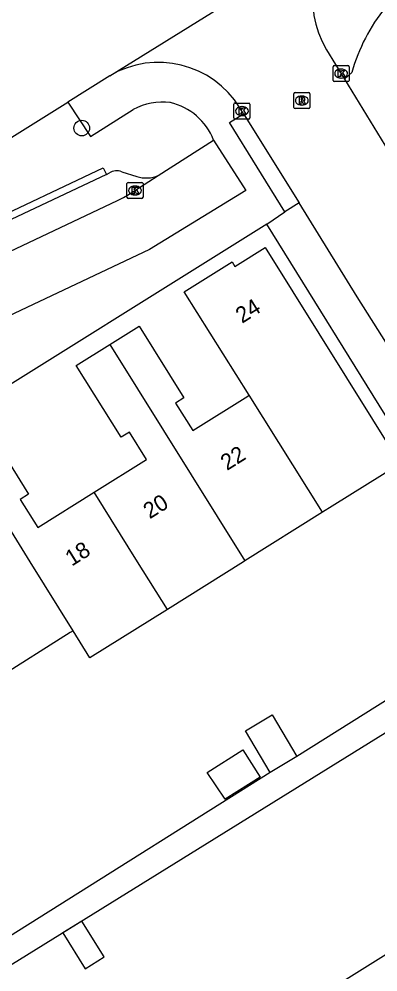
# Model space of a CAD drawing. Extents: x 157767 to 159171, y 387842 to 389425.
# Drawn here: x 158324.1 to 158346.5, y 388224.4 to 388283.9 of the extents above; entities that cross this region are included whole.
import ezdxf

# ---------------------------------------------------------------- set-up
doc = ezdxf.new("R2010")
doc.units = 0
for name, color, linetype in [('IMGEO_Boom', 7, 'Continuous'), ('IMGEO_Fietspad_open', 7, 'Continuous'), ('IMGEO_Kolk', 7, 'Continuous'), ('IMGEO_Pand', 7, 'Continuous'), ('IMGEO_Pand_nummerreeks', 7, 'Continuous'), ('IMGEO_Parkeervlak_open', 7, 'Continuous'), ('IMGEO_Rijbaan_lokaal_gesloten', 7, 'Continuous'), ('IMGEO_Rijbaan_lokaal_open', 7, 'Continuous'), ('IMGEO_Rioolput', 7, 'Continuous'), ('IMGEO_Voetpad_open', 7, 'Continuous')]:
    doc.layers.add(name, color=color, linetype=linetype)

msp = doc.modelspace()

# ---------------------------------------------------------------- linework, layer by layer
at = {"layer": 'IMGEO_Boom'}
msp.add_circle((158328.047, 388277.051), 0.489, dxfattribs=at)
at = {"layer": 'IMGEO_Fietspad_open'}
msp.add_lwpolyline([(158344.91, 388280.527), (158344.452, 388280.106)], dxfattribs=at)
msp.add_arc((158356.036, 388277.36), 11.568, 141.36415, 164.11301, dxfattribs=at)
at = {"layer": 'IMGEO_Kolk'}
for p, q in [((158343.74, 388280.027), (158343.74, 388280.879)), ((158343.815, 388280.953), (158344.667, 388280.953)), ((158344.228, 388280.733), (158344.253, 388280.733)), ((158344.741, 388280.879), (158344.741, 388280.027)), ((158344.667, 388279.953), (158343.815, 388279.953)), ((158344.251, 388280.173), (158344.226, 388280.173)), ((158337.621, 388278.616), (158338.473, 388278.616)), ((158337.546, 388277.69), (158337.546, 388278.542)), ((158338.034, 388278.396), (158338.059, 388278.396)), ((158338.547, 388278.542), (158338.547, 388277.69)), ((158338.473, 388277.616), (158337.621, 388277.616)), ((158338.057, 388277.836), (158338.032, 388277.836)), ((158330.869, 388272.732), (158330.869, 388273.584)), ((158330.944, 388273.658), (158331.796, 388273.658)), ((158331.357, 388273.438), (158331.382, 388273.438)), ((158331.87, 388273.584), (158331.87, 388272.732)), ((158331.796, 388272.658), (158330.944, 388272.658)), ((158331.38, 388272.878), (158331.355, 388272.878))]:
    msp.add_line(p, q, dxfattribs=at)
for points in [[(158343.74, 388280.027), (158343.74, 388280.879)], [(158343.815, 388280.953), (158344.667, 388280.953)], [(158344.061, 388280.653), (158344.184, 388280.653), (158344.184, 388280.502), (158344.314, 388280.653), (158344.478, 388280.653), (158344.332, 388280.502), (158344.485, 388280.253), (158344.333, 388280.253), (158344.248, 388280.417), (158344.184, 388280.35), (158344.184, 388280.253), (158344.061, 388280.253), (158344.061, 388280.653)], [(158344.741, 388280.879), (158344.741, 388280.027)], [(158344.667, 388279.953), (158343.815, 388279.953)], [(158337.621, 388278.616), (158338.473, 388278.616)], [(158337.546, 388277.69), (158337.546, 388278.542)], [(158337.867, 388278.316), (158337.99, 388278.316), (158337.99, 388278.165), (158338.12, 388278.316), (158338.284, 388278.316), (158338.138, 388278.165), (158338.291, 388277.916), (158338.139, 388277.916), (158338.054, 388278.08), (158337.99, 388278.013), (158337.99, 388277.916), (158337.867, 388277.916), (158337.867, 388278.316)], [(158338.547, 388278.542), (158338.547, 388277.69)], [(158338.473, 388277.616), (158337.621, 388277.616)], [(158330.869, 388272.732), (158330.869, 388273.584)], [(158330.944, 388273.658), (158331.796, 388273.658)], [(158331.19, 388273.358), (158331.313, 388273.358), (158331.313, 388273.207), (158331.443, 388273.358), (158331.607, 388273.358), (158331.461, 388273.207), (158331.614, 388272.958), (158331.462, 388272.958), (158331.377, 388273.122), (158331.313, 388273.055), (158331.313, 388272.958), (158331.19, 388272.958), (158331.19, 388273.358)], [(158331.87, 388273.584), (158331.87, 388272.732)], [(158331.796, 388272.658), (158330.944, 388272.658)]]:
    msp.add_lwpolyline(points, dxfattribs=at)
for centre, start, end in [((158343.817, 388280.877), 91.55205, 178.44795), ((158343.817, 388280.877), 91.55205, 178.44795), ((158344.665, 388280.877), 1.55205, 88.44795), ((158344.665, 388280.877), 1.55205, 88.44795), ((158343.817, 388280.029), 181.55205, 268.44795), ((158343.817, 388280.029), 181.55205, 268.44795), ((158344.665, 388280.029), 271.55205, 358.44795), ((158344.665, 388280.029), 271.55205, 358.44795), ((158337.623, 388278.54), 91.55205, 178.44795), ((158337.623, 388278.54), 91.55205, 178.44795), ((158338.471, 388278.54), 1.55205, 88.44795), ((158338.471, 388278.54), 1.55205, 88.44795), ((158337.623, 388277.692), 181.55205, 268.44795), ((158337.623, 388277.692), 181.55205, 268.44795), ((158338.471, 388277.692), 271.55205, 358.44795), ((158338.471, 388277.692), 271.55205, 358.44795), ((158330.946, 388273.582), 91.55205, 178.44795), ((158330.946, 388273.582), 91.55205, 178.44795), ((158331.794, 388273.582), 1.55205, 88.44795), ((158331.794, 388273.582), 1.55205, 88.44795), ((158330.946, 388272.734), 181.55205, 268.44795), ((158330.946, 388272.734), 181.55205, 268.44795), ((158331.794, 388272.734), 271.55205, 358.44795), ((158331.794, 388272.734), 271.55205, 358.44795)]:
    msp.add_arc(centre, 0.0765, start, end, dxfattribs=at)
for centre, major_axis, ratio, start_param, end_param in [((158344.227, 388280.453), (-0.387, 0.002), 0.722429, 4.712389, 7.853982), ((158344.252, 388280.453), (-0.39, 0.002), 0.717154, 1.570796, 4.712389), ((158338.033, 388278.116), (-0.387, 0.002), 0.722429, 4.712389, 7.853982), ((158338.058, 388278.116), (-0.39, 0.002), 0.717154, 1.570796, 4.712389), ((158331.356, 388273.158), (-0.387, 0.002), 0.722429, 4.712389, 7.853982), ((158331.381, 388273.158), (-0.39, 0.002), 0.717154, 1.570796, 4.712389)]:
    msp.add_ellipse(centre, major_axis=major_axis, ratio=ratio, start_param=start_param, end_param=end_param, dxfattribs=at)
at = {"layer": 'IMGEO_Pand'}
for points in [[(158338.497, 388260.387), (158334.45, 388266.841), (158337.437, 388268.697), (158337.606, 388268.425), (158339.488, 388269.602), (158347.922, 388256.115), (158343.683, 388253.464), (158343.076, 388253.084)], [(158329.796, 388263.551), (158331.627, 388264.696), (158334.427, 388260.219), (158333.903, 388259.892), (158334.971, 388258.183), (158338.41, 388260.333), (158338.497, 388260.387)], [(158328.825, 388254.343), (158332.09, 388256.385), (158331.023, 388258.091), (158330.496, 388257.761), (158327.697, 388262.238), (158329.796, 388263.551)], [(158329.796, 388263.551), (158338.237, 388250.058)], [(158343.076, 388253.084), (158338.497, 388260.387)], [(158320.14, 388257.57), (158321.928, 388258.688), (158324.727, 388254.211), (158324.203, 388253.884), (158325.296, 388252.136), (158328.825, 388254.343)], [(158327.504, 388245.688), (158324.822, 388250), (158320.14, 388257.57)], [(158333.392, 388247.027), (158331.536, 388250), (158328.825, 388254.343)], [(158343.076, 388253.084), (158338.237, 388250.058)], [(158338.237, 388250.058), (158338.145, 388250), (158333.392, 388247.027)], [(158333.392, 388247.027), (158328.553, 388244.001), (158327.504, 388245.688)], [(158327.504, 388245.688), (158327.332, 388245.58), (158322.699, 388242.682)], [(158339.805, 388236.853), (158338.261, 388239.455), (158339.941, 388240.451), (158341.485, 388237.85)], [(158335.882, 388236.859), (158338.103, 388238.266), (158339.181, 388236.564), (158336.991, 388235.177), (158335.882, 388236.859)], [(158341.485, 388237.85), (158339.805, 388236.853)], [(158326.863, 388226.839), (158328.257, 388224.609), (158329.443, 388225.351), (158328.049, 388227.581), (158326.863, 388226.839)], [(158342.715, 388222.816), (158347.548, 388225.838)]]:
    msp.add_lwpolyline(points, dxfattribs=at)
at = {"layer": 'IMGEO_Parkeervlak_open'}
for points in [[(158329.591, 388274.165), (158329.769, 388274.255)], [(158330.541, 388274.327), (158331.492, 388274.027)]]:
    msp.add_lwpolyline(points, dxfattribs=at)
for centre, radius, start, end in [((158330.226, 388273.528), 0.859, 68.50556, 122.15091), ((158332.071, 388275.861), 1.923, 252.47339, 293.10575)]:
    msp.add_arc(centre, radius, start, end, dxfattribs=at)
at = {"layer": 'IMGEO_Rijbaan_lokaal_gesloten'}
for points in [[(158329.789, 388280.317), (158345.174, 388289.863)], [(158329.789, 388280.317), (158327.166, 388278.678)], [(158282.323, 388250.72), (158291.553, 388256.471), (158304.666, 388264.637), (158318.32, 388273.151), (158327.166, 388278.678)]]:
    msp.add_lwpolyline(points, dxfattribs=at)
at = {"layer": 'IMGEO_Rijbaan_lokaal_open'}
for points in [[(158343.332, 388281.936), (158344.452, 388280.106)], [(158344.452, 388280.106), (158347.426, 388275.246)], [(158338.153, 388277.947), (158337.92, 388278.322)], [(158338.153, 388277.947), (158341.612, 388272.378)], [(158336.27, 388276.303), (158338.282, 388273.157), (158332.269, 388269.479), (158316.929, 388262.243), (158308.753, 388257.124)], [(158332.826, 388274.092), (158336.27, 388276.303)], [(158307.852, 388260.817), (158315.177, 388265.398), (158330.276, 388272.527), (158330.654, 388272.713), (158331.015, 388272.929), (158332.826, 388274.092)], [(158375.84, 388217.622), (158374.327, 388219.999), (158367.819, 388230.333), (158359.302, 388244.112), (158355.646, 388250), (158353.084, 388254.126), (158345.243, 388266.533), (158341.612, 388272.378)]]:
    msp.add_lwpolyline(points, dxfattribs=at)
for centre, radius, start, end in [((158348.281, 388284.964), 5.801, 122.37945, 211.45718), ((158332.834, 388275.162), 5.987, 31.85406, 120.57472)]:
    msp.add_arc(centre, radius, start, end, dxfattribs=at)
at = {"layer": 'IMGEO_Rioolput'}
for p, q in [((158341.289, 388278.344), (158341.289, 388279.196)), ((158341.364, 388279.27), (158342.216, 388279.27)), ((158342.29, 388279.196), (158342.29, 388278.344)), ((158341.777, 388279.05), (158341.802, 388279.05)), ((158342.216, 388278.27), (158341.364, 388278.27)), ((158341.8, 388278.49), (158341.775, 388278.49))]:
    msp.add_line(p, q, dxfattribs=at)
for points in [[(158341.289, 388278.344), (158341.289, 388279.196)], [(158341.364, 388279.27), (158342.216, 388279.27)], [(158342.29, 388279.196), (158342.29, 388278.344)], [(158341.878, 388278.968), (158341.626, 388278.97), (158341.626, 388278.57)], [(158341.626, 388278.57), (158341.75, 388278.57), (158341.75, 388278.732), (158341.761, 388278.732)], [(158341.804, 388278.889), (158341.75, 388278.889), (158341.75, 388278.808)], [(158341.75, 388278.808), (158341.802, 388278.808)], [(158341.808, 388278.703), (158341.879, 388278.57), (158342.019, 388278.57), (158341.954, 388278.696)], [(158342.216, 388278.27), (158341.364, 388278.27)]]:
    msp.add_lwpolyline(points, dxfattribs=at)
for centre, radius, start, end in [((158341.366, 388279.194), 0.0765, 91.55205, 178.44795), ((158341.366, 388279.194), 0.0765, 91.55205, 178.44795), ((158342.214, 388279.194), 0.0765, 1.55205, 88.44795), ((158342.214, 388279.194), 0.0765, 1.55205, 88.44795), ((158341.76, 388278.679), 0.0533, 26.02933, 88.69889), ((158341.786, 388278.997), 0.19, 274.7715, 282.96867), ((158341.81, 388278.793), 0.0964, 77.00612, 93.18647), ((158341.824, 388278.85), 0.0378, 276.66336, 79.67722), ((158341.877, 388278.858), 0.109, 350.36119, 89.41601), ((158341.875, 388278.858), 0.112, 277.58423, 350.98172), ((158341.859, 388278.643), 0.108, 29.51342, 73.79051), ((158341.366, 388278.346), 0.0765, 181.55205, 268.44795), ((158341.366, 388278.346), 0.0765, 181.55205, 268.44795), ((158342.214, 388278.346), 0.0765, 271.55205, 358.44795), ((158342.214, 388278.346), 0.0765, 271.55205, 358.44795)]:
    msp.add_arc(centre, radius, start, end, dxfattribs=at)
for centre, major_axis, ratio, start_param, end_param in [((158341.776, 388278.77), (-0.387, 0.002), 0.722429, 4.712389, 7.853982), ((158341.801, 388278.77), (-0.39, 0.002), 0.717154, 1.570796, 4.712389)]:
    msp.add_ellipse(centre, major_axis=major_axis, ratio=ratio, start_param=start_param, end_param=end_param, dxfattribs=at)
at = {"layer": 'IMGEO_Voetpad_open'}
for points in [[(158327.166, 388278.678), (158328.583, 388276.523), (158331.262, 388278.203)], [(158340.729, 388271.829), (158337.27, 388277.398), (158338.153, 388277.947)], [(158309.208, 388263.753), (158308.983, 388264.139), (158314.08, 388267.335), (158329.392, 388274.564), (158329.591, 388274.165)], [(158329.591, 388274.165), (158314.321, 388266.951), (158309.208, 388263.753)], [(158341.612, 388272.378), (158340.729, 388271.829)], [(158339.598, 388271.048), (158340.729, 388271.829)], [(158339.598, 388271.048), (158319.528, 388258.548)], [(158354.972, 388246.308), (158347.736, 388257.953), (158339.598, 388271.048)], [(158354.972, 388246.308), (158341.485, 388237.85)], [(158317.43, 388208.862), (158311.985, 388217.662), (158352.633, 388242.812)], [(158339.805, 388236.853), (158310.937, 388218.725), (158304.231, 388217.941), (158302.989, 388219.558), (158300.563, 388218.345), (158302.062, 388215.346), (158303.653, 388216.141), (158310.772, 388216.911), (158324.05, 388195.698)]]:
    msp.add_lwpolyline(points, dxfattribs=at)
for centre, radius, start, end in [((158333.083, 388274.916), 3.758, 82.45641, 118.98017), ((158332.739, 388274.956), 3.779, 20.88749, 77.20606)]:
    msp.add_arc(centre, radius, start, end, dxfattribs=at)

# ---------------------------------------------------------------- texts
at = {"layer": 'IMGEO_Pand_nummerreeks'}
for s, rotation, p in [('24', 32.02261, (158338.056, 388264.838)), ('22', 32.01115, (158337.115, 388255.656)), ('20', 32.00905, (158332.289, 388252.638)), ('18', 32.01688, (158327.417, 388249.687))]:
    msp.add_text(s, height=1, rotation=rotation, dxfattribs=at).set_placement(p)

doc.saveas('drawing.dxf')
